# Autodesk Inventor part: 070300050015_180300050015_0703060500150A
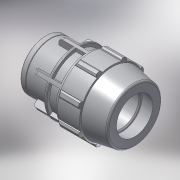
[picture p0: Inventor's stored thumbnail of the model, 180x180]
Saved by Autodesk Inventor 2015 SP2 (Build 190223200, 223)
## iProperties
Created: 2017-02
Part Number: 070300050015_180300050015_0703060500150A
Material: PVC-Piping
Description: PLASSON FEMALE ADAPTOR 50-1.1/2"
Document SubType Name: Modeling
Designer: KIM
Mass: 92.6774 g
Surface Area: 199.44 cm^2
Volume: 66.1981 cm^3
Density: 1.4 g/cm^3
Appearance: Smooth - White
Author: KIM
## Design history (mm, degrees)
derived "07030.ipt"
feature "Solid1::07030.ipt"
tag "TaggingFeature1"
body "Solid1"
other parameters: "d4" = 17.57143, "d5" = 30.75, "d7" = 96, "d9" = 17.57143, "d11" = 3.51429, "d12" = 76.8, "d13" = 120 deg, "d14" = 75, "d15" = 10 deg, "d16" = 86.4, "d18" = 2.5, "d19" = 35 deg, "d20" = 17.5 deg, "d21" = 89.28, "d23" = 0, "d25" = 360 deg, "d27" = 1.92, "d34" = 4.8, "d35" = 36.9, "d36" = 0, "d42" = 30.75, "d43" = 2.88, "d46" = 1.5, "d49" = 93, "d51" = 123, "d53" = 1, "d55" = 360 deg, "d61" = 25, "d63" = 44.845, "d64" = 41, "d65" = 4.8, "d66" = 0.5, "d67" = 1, "d68" = 7.5, "d69" = 69.12, "d70" = 2.4, "E_" = 96, "H_" = 123, "l_" = 93, "l_2" = 25, "Rp_" = 44.845
